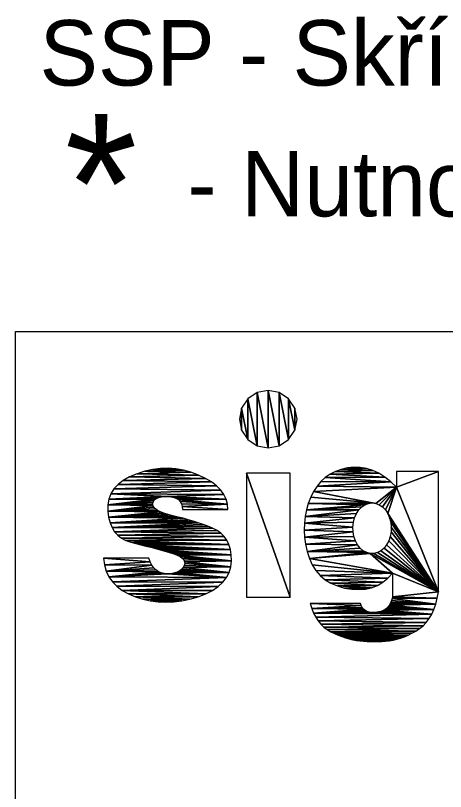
# Model space of a CAD drawing. Extents: x -614134 to -613504, y -1110668 to -1110371.
# Drawn here: x -613676 to -613656.3, y -1110630.88 to -1110595.29 of the extents above; entities that cross this region are included whole.
import ezdxf

# ---------------------------------------------------------------- set-up
doc = ezdxf.new("R2010")
doc.units = 0
doc.layers.add('Vrstva 1', color=7, linetype='Continuous')

msp = doc.modelspace()

# ---------------------------------------------------------------- linework, layer by layer
at = {"layer": 'Vrstva 1'}
for points in [[(-613676, -1110609.774), (-613511, -1110609.774), (-613511, -1110662), (-613676, -1110662)], [(-613676, -1110609.774), (-613511, -1110609.774), (-613511, -1110662), (-613676, -1110662)], [(-613664.926, -1110612.582), (-613664.42, -1110615.122), (-613664.42, -1110612.482)], [(-613664.42, -1110612.482), (-613663.915, -1110615.022), (-613663.915, -1110612.582)], [(-613663.915, -1110615.022), (-613664.42, -1110612.482), (-613664.42, -1110615.122)], [(-613665.354, -1110612.868), (-613664.926, -1110615.022), (-613664.926, -1110612.582)], [(-613664.42, -1110615.122), (-613664.926, -1110612.582), (-613664.926, -1110615.022)], [(-613663.915, -1110612.582), (-613663.487, -1110614.736), (-613663.487, -1110612.868)], [(-613663.487, -1110614.736), (-613663.915, -1110612.582), (-613663.915, -1110615.022)], [(-613665.64, -1110613.298), (-613665.354, -1110614.736), (-613665.354, -1110612.868)], [(-613664.926, -1110615.022), (-613665.354, -1110612.868), (-613665.354, -1110614.736)], [(-613663.487, -1110612.868), (-613663.201, -1110614.308), (-613663.201, -1110613.298)], [(-613663.201, -1110614.308), (-613663.487, -1110612.868), (-613663.487, -1110614.736)], [(-613665.74, -1110613.802), (-613665.64, -1110614.308), (-613665.64, -1110613.298)], [(-613665.354, -1110614.736), (-613665.64, -1110613.298), (-613665.64, -1110614.308)], [(-613663.1, -1110613.802), (-613663.201, -1110613.298), (-613663.201, -1110614.308)], [(-613669.359, -1110616.064), (-613669.714, -1110616.108), (-613668.656, -1110616.078)], [(-613669.006, -1110616.054), (-613669.359, -1110616.064), (-613668.656, -1110616.078)], [(-613660.788, -1110616.038), (-613661.076, -1110616.106), (-613659.913, -1110616.062)], [(-613659.913, -1110616.062), (-613661.076, -1110616.106), (-613659.63, -1110616.152)], [(-613660.492, -1110616.006), (-613660.788, -1110616.038), (-613660.201, -1110616.012)], [(-613660.201, -1110616.012), (-613660.788, -1110616.038), (-613659.913, -1110616.062)], [(-613670.434, -1110616.302), (-613670.772, -1110616.444), (-613667.621, -1110616.362)], [(-613667.621, -1110616.362), (-613670.772, -1110616.444), (-613667.301, -1110616.516)], [(-613670.073, -1110616.188), (-613670.434, -1110616.302), (-613667.963, -1110616.232)], [(-613667.963, -1110616.232), (-613670.434, -1110616.302), (-613667.621, -1110616.362)], [(-613669.714, -1110616.108), (-613670.073, -1110616.188), (-613668.308, -1110616.138)], [(-613668.308, -1110616.138), (-613670.073, -1110616.188), (-613667.963, -1110616.232)], [(-613668.656, -1110616.078), (-613669.714, -1110616.108), (-613668.308, -1110616.138)], [(-613663.42, -1110621.962), (-613663.42, -1110616.282), (-613665.42, -1110616.282)], [(-613665.42, -1110616.282), (-613665.42, -1110621.962), (-613663.42, -1110621.962)], [(-613661.585, -1110616.33), (-613661.806, -1110616.482), (-613659.077, -1110616.454)], [(-613661.341, -1110616.204), (-613661.585, -1110616.33), (-613659.351, -1110616.282)], [(-613659.351, -1110616.282), (-613661.585, -1110616.33), (-613659.077, -1110616.454)], [(-613661.076, -1110616.106), (-613661.341, -1110616.204), (-613659.63, -1110616.152)], [(-613659.63, -1110616.152), (-613661.341, -1110616.204), (-613659.351, -1110616.282)], [(-613656.62, -1110616.202), (-613658.54, -1110616.922), (-613656.62, -1110621.722)], [(-613658.54, -1110616.202), (-613658.54, -1110616.922), (-613656.62, -1110616.202)], [(-613671.061, -1110616.608), (-613671.302, -1110616.79), (-613667.025, -1110616.682)], [(-613667.025, -1110616.682), (-613671.302, -1110616.79), (-613666.791, -1110616.86)], [(-613670.772, -1110616.444), (-613671.061, -1110616.608), (-613667.301, -1110616.516)], [(-613667.301, -1110616.516), (-613671.061, -1110616.608), (-613667.025, -1110616.682)], [(-613662.006, -1110616.666), (-613662.185, -1110616.876), (-613658.807, -1110616.668)], [(-613658.807, -1110616.668), (-613662.185, -1110616.876), (-613658.54, -1110616.922)], [(-613661.806, -1110616.482), (-613662.006, -1110616.666), (-613658.807, -1110616.668)], [(-613659.077, -1110616.454), (-613661.806, -1110616.482), (-613658.807, -1110616.668)], [(-613671.494, -1110616.994), (-613671.637, -1110617.22), (-613666.6, -1110617.052)], [(-613666.6, -1110617.052), (-613671.637, -1110617.22), (-613666.452, -1110617.256)], [(-613671.302, -1110616.79), (-613671.494, -1110616.994), (-613666.791, -1110616.86)], [(-613666.791, -1110616.86), (-613671.494, -1110616.994), (-613666.6, -1110617.052)], [(-613662.341, -1110617.116), (-613662.476, -1110617.384), (-613659.66, -1110617.642)], [(-613662.185, -1110616.876), (-613662.341, -1110617.116), (-613658.54, -1110616.922)], [(-613658.54, -1110616.922), (-613662.341, -1110617.116), (-613659.494, -1110617.664)], [(-613662.341, -1110617.116), (-613659.66, -1110617.642), (-613659.494, -1110617.664)], [(-613658.54, -1110616.922), (-613659.494, -1110617.664), (-613659.333, -1110617.726)], [(-613658.54, -1110616.922), (-613659.333, -1110617.726), (-613659.185, -1110617.826)], [(-613658.54, -1110616.922), (-613659.185, -1110617.826), (-613659.053, -1110617.962)], [(-613658.54, -1110616.922), (-613659.053, -1110617.962), (-613658.944, -1110618.13)], [(-613658.54, -1110616.922), (-613658.944, -1110618.13), (-613656.62, -1110621.722)], [(-613671.732, -1110617.464), (-613671.778, -1110617.73), (-613669.602, -1110617.474)], [(-613669.602, -1110617.474), (-613671.778, -1110617.73), (-613669.658, -1110617.532)], [(-613671.637, -1110617.22), (-613671.732, -1110617.464), (-613669.179, -1110617.35)], [(-613669.179, -1110617.35), (-613671.732, -1110617.464), (-613669.314, -1110617.364)], [(-613669.314, -1110617.364), (-613671.732, -1110617.464), (-613669.43, -1110617.39)], [(-613669.43, -1110617.39), (-613671.732, -1110617.464), (-613669.526, -1110617.426)], [(-613669.526, -1110617.426), (-613671.732, -1110617.464), (-613669.602, -1110617.474)], [(-613671.637, -1110617.22), (-613669.023, -1110617.346), (-613666.452, -1110617.256)], [(-613671.637, -1110617.22), (-613669.179, -1110617.35), (-613669.023, -1110617.346)], [(-613666.452, -1110617.256), (-613669.023, -1110617.346), (-613666.347, -1110617.474)], [(-613669.023, -1110617.346), (-613668.868, -1110617.358), (-613666.347, -1110617.474)], [(-613668.868, -1110617.358), (-613668.733, -1110617.386), (-613666.347, -1110617.474)], [(-613668.733, -1110617.386), (-613668.618, -1110617.434), (-613666.347, -1110617.474)], [(-613668.618, -1110617.434), (-613668.523, -1110617.5), (-613666.347, -1110617.474)], [(-613666.347, -1110617.474), (-613668.523, -1110617.5), (-613666.285, -1110617.702)], [(-613662.476, -1110617.384), (-613662.587, -1110617.67), (-613659.66, -1110617.642)], [(-613669.658, -1110617.532), (-613671.778, -1110617.73), (-613669.694, -1110617.6)], [(-613669.694, -1110617.6), (-613671.778, -1110617.73), (-613669.711, -1110617.68)], [(-613669.711, -1110617.68), (-613671.778, -1110617.73), (-613669.702, -1110617.764)], [(-613671.778, -1110617.73), (-613671.776, -1110618.016), (-613669.702, -1110617.764)], [(-613669.702, -1110617.764), (-613671.776, -1110618.016), (-613669.663, -1110617.842)], [(-613669.663, -1110617.842), (-613671.776, -1110618.016), (-613669.594, -1110617.918)], [(-613668.523, -1110617.5), (-613668.449, -1110617.584), (-613666.285, -1110617.702)], [(-613668.449, -1110617.584), (-613668.394, -1110617.686), (-613666.285, -1110617.702)], [(-613668.394, -1110617.686), (-613668.359, -1110617.806), (-613666.285, -1110617.702)], [(-613666.285, -1110617.702), (-613668.359, -1110617.806), (-613666.266, -1110617.944)], [(-613668.359, -1110617.806), (-613668.345, -1110617.944), (-613666.266, -1110617.944)], [(-613662.587, -1110617.67), (-613662.671, -1110617.962), (-613659.988, -1110617.726)], [(-613659.988, -1110617.726), (-613662.671, -1110617.962), (-613660.136, -1110617.826)], [(-613660.136, -1110617.826), (-613662.671, -1110617.962), (-613660.268, -1110617.962)], [(-613659.66, -1110617.642), (-613662.587, -1110617.67), (-613659.827, -1110617.664)], [(-613659.827, -1110617.664), (-613662.587, -1110617.67), (-613659.988, -1110617.726)], [(-613669.594, -1110617.918), (-613671.776, -1110618.016), (-613669.494, -1110617.988)], [(-613669.494, -1110617.988), (-613671.776, -1110618.016), (-613669.364, -1110618.056)], [(-613671.776, -1110618.016), (-613671.736, -1110618.296), (-613669.364, -1110618.056)], [(-613669.364, -1110618.056), (-613671.736, -1110618.296), (-613669.203, -1110618.118)], [(-613669.203, -1110618.118), (-613671.736, -1110618.296), (-613669.012, -1110618.178)], [(-613669.012, -1110618.178), (-613671.736, -1110618.296), (-613668.79, -1110618.232)], [(-613660.268, -1110617.962), (-613662.73, -1110618.262), (-613660.377, -1110618.13)], [(-613662.671, -1110617.962), (-613662.73, -1110618.262), (-613660.268, -1110617.962)], [(-613660.377, -1110618.13), (-613662.73, -1110618.262), (-613660.461, -1110618.32)], [(-613658.944, -1110618.13), (-613658.86, -1110618.32), (-613656.62, -1110621.722)], [(-613668.79, -1110618.232), (-613671.736, -1110618.296), (-613668.554, -1110618.288)], [(-613668.554, -1110618.288), (-613671.736, -1110618.296), (-613668.321, -1110618.348)], [(-613671.736, -1110618.296), (-613671.67, -1110618.548), (-613668.321, -1110618.348)], [(-613668.321, -1110618.348), (-613671.67, -1110618.548), (-613668.09, -1110618.412)], [(-613668.09, -1110618.412), (-613671.67, -1110618.548), (-613667.861, -1110618.48)], [(-613667.861, -1110618.48), (-613671.67, -1110618.548), (-613667.635, -1110618.554)], [(-613671.67, -1110618.548), (-613671.578, -1110618.772), (-613667.635, -1110618.554)], [(-613667.635, -1110618.554), (-613671.578, -1110618.772), (-613667.41, -1110618.63)], [(-613662.73, -1110618.262), (-613662.763, -1110618.57), (-613660.461, -1110618.32)], [(-613660.461, -1110618.32), (-613662.763, -1110618.57), (-613660.516, -1110618.528)], [(-613660.516, -1110618.528), (-613662.763, -1110618.57), (-613660.539, -1110618.748)], [(-613658.86, -1110618.32), (-613658.805, -1110618.528), (-613656.62, -1110621.722)], [(-613658.805, -1110618.528), (-613658.781, -1110618.748), (-613656.62, -1110621.722)], [(-613667.41, -1110618.63), (-613671.578, -1110618.772), (-613667.189, -1110618.712)], [(-613667.189, -1110618.712), (-613671.578, -1110618.772), (-613666.969, -1110618.798)], [(-613671.578, -1110618.772), (-613671.46, -1110618.964), (-613666.969, -1110618.798)], [(-613666.969, -1110618.798), (-613671.46, -1110618.964), (-613666.764, -1110618.9)], [(-613666.764, -1110618.9), (-613671.46, -1110618.964), (-613666.587, -1110619.024)], [(-613662.763, -1110618.57), (-613662.77, -1110618.884), (-613660.539, -1110618.748)], [(-613660.539, -1110618.748), (-613662.77, -1110618.884), (-613660.532, -1110618.968)], [(-613662.77, -1110618.884), (-613662.752, -1110619.206), (-613660.532, -1110618.968)], [(-613658.781, -1110618.748), (-613658.789, -1110618.968), (-613656.62, -1110621.722)], [(-613671.46, -1110618.964), (-613671.315, -1110619.128), (-613666.587, -1110619.024)], [(-613666.587, -1110619.024), (-613671.315, -1110619.128), (-613666.438, -1110619.174)], [(-613671.315, -1110619.128), (-613671.144, -1110619.262), (-613666.438, -1110619.174)], [(-613666.438, -1110619.174), (-613671.144, -1110619.262), (-613666.317, -1110619.35)], [(-613671.144, -1110619.262), (-613670.947, -1110619.366), (-613666.317, -1110619.35)], [(-613660.532, -1110618.968), (-613662.752, -1110619.206), (-613660.492, -1110619.182)], [(-613660.492, -1110619.182), (-613662.752, -1110619.206), (-613660.423, -1110619.382)], [(-613662.752, -1110619.206), (-613662.707, -1110619.536), (-613660.423, -1110619.382)], [(-613658.829, -1110619.182), (-613658.898, -1110619.382), (-613656.62, -1110621.722)], [(-613658.789, -1110618.968), (-613658.829, -1110619.182), (-613656.62, -1110621.722)], [(-613666.317, -1110619.35), (-613670.947, -1110619.366), (-613666.223, -1110619.55)], [(-613670.947, -1110619.366), (-613670.723, -1110619.44), (-613666.223, -1110619.55)], [(-613670.723, -1110619.44), (-613670.489, -1110619.5), (-613666.223, -1110619.55)], [(-613670.489, -1110619.5), (-613670.257, -1110619.56), (-613666.223, -1110619.55)], [(-613666.223, -1110619.55), (-613670.257, -1110619.56), (-613666.157, -1110619.774)], [(-613670.257, -1110619.56), (-613670.03, -1110619.618), (-613666.157, -1110619.774)], [(-613670.03, -1110619.618), (-613669.806, -1110619.678), (-613666.157, -1110619.774)], [(-613660.423, -1110619.382), (-613662.707, -1110619.536), (-613660.326, -1110619.562)], [(-613662.707, -1110619.536), (-613662.636, -1110619.872), (-613660.326, -1110619.562)], [(-613660.326, -1110619.562), (-613662.636, -1110619.872), (-613660.204, -1110619.714)], [(-613658.995, -1110619.562), (-613659.116, -1110619.714), (-613656.62, -1110621.722)], [(-613658.898, -1110619.382), (-613658.995, -1110619.562), (-613656.62, -1110621.722)], [(-613669.806, -1110619.678), (-613669.586, -1110619.736), (-613666.157, -1110619.774)], [(-613669.586, -1110619.736), (-613669.369, -1110619.794), (-613666.157, -1110619.774)], [(-613666.157, -1110619.774), (-613669.369, -1110619.794), (-613666.119, -1110620.022)], [(-613669.369, -1110619.794), (-613669.156, -1110619.852), (-613666.119, -1110620.022)], [(-613669.156, -1110619.852), (-613668.946, -1110619.91), (-613666.119, -1110620.022)], [(-613668.946, -1110619.91), (-613668.754, -1110619.97), (-613666.119, -1110620.022)], [(-613668.754, -1110619.97), (-613668.592, -1110620.036), (-613666.119, -1110620.022)], [(-613660.204, -1110619.714), (-613662.636, -1110619.872), (-613660.064, -1110619.834)], [(-613660.064, -1110619.834), (-613662.636, -1110619.872), (-613659.908, -1110619.916)], [(-613662.636, -1110619.872), (-613662.536, -1110620.194), (-613659.908, -1110619.916)], [(-613659.908, -1110619.916), (-613662.536, -1110620.194), (-613659.744, -1110619.958)], [(-613659.744, -1110619.958), (-613662.536, -1110620.194), (-613658.728, -1110620.868)], [(-613659.744, -1110619.958), (-613658.728, -1110620.868), (-613656.62, -1110621.722)], [(-613656.62, -1110621.722), (-613659.577, -1110619.958), (-613659.744, -1110619.958)], [(-613659.413, -1110619.916), (-613659.577, -1110619.958), (-613656.62, -1110621.722)], [(-613659.257, -1110619.834), (-613659.413, -1110619.916), (-613656.62, -1110621.722)], [(-613659.116, -1110619.714), (-613659.257, -1110619.834), (-613656.62, -1110621.722)], [(-613669.827, -1110620.346), (-613669.888, -1110620.176), (-613671.969, -1110620.176)], [(-613671.969, -1110620.176), (-613671.925, -1110620.484), (-613669.827, -1110620.346)], [(-613666.119, -1110620.022), (-613668.592, -1110620.036), (-613666.108, -1110620.296)], [(-613668.592, -1110620.036), (-613668.462, -1110620.104), (-613666.108, -1110620.296)], [(-613668.462, -1110620.104), (-613668.362, -1110620.178), (-613666.108, -1110620.296)], [(-613668.362, -1110620.178), (-613668.294, -1110620.256), (-613666.108, -1110620.296)], [(-613668.294, -1110620.256), (-613668.256, -1110620.338), (-613666.108, -1110620.296)], [(-613666.108, -1110620.296), (-613668.256, -1110620.338), (-613666.135, -1110620.572)], [(-613662.536, -1110620.194), (-613662.403, -1110620.486), (-613658.728, -1110620.868)], [(-613669.827, -1110620.346), (-613671.925, -1110620.484), (-613669.753, -1110620.492)], [(-613671.925, -1110620.484), (-613671.842, -1110620.766), (-613669.753, -1110620.492)], [(-613669.753, -1110620.492), (-613671.842, -1110620.766), (-613669.667, -1110620.616)], [(-613669.667, -1110620.616), (-613671.842, -1110620.766), (-613669.568, -1110620.716)], [(-613668.381, -1110620.68), (-613668.456, -1110620.744), (-613666.208, -1110620.828)], [(-613668.32, -1110620.604), (-613668.381, -1110620.68), (-613666.208, -1110620.828)], [(-613668.273, -1110620.516), (-613668.32, -1110620.604), (-613666.135, -1110620.572)], [(-613666.135, -1110620.572), (-613668.32, -1110620.604), (-613666.208, -1110620.828)], [(-613668.249, -1110620.424), (-613668.273, -1110620.516), (-613666.135, -1110620.572)], [(-613668.256, -1110620.338), (-613668.249, -1110620.424), (-613666.135, -1110620.572)], [(-613662.403, -1110620.486), (-613662.238, -1110620.744), (-613658.728, -1110620.868)], [(-613669.568, -1110620.716), (-613671.842, -1110620.766), (-613669.456, -1110620.796)], [(-613671.842, -1110620.766), (-613671.718, -1110621.024), (-613669.456, -1110620.796)], [(-613669.456, -1110620.796), (-613671.718, -1110621.024), (-613669.333, -1110620.85)], [(-613669.333, -1110620.85), (-613671.718, -1110621.024), (-613669.197, -1110620.884)], [(-613669.197, -1110620.884), (-613671.718, -1110621.024), (-613669.049, -1110620.894)], [(-613669.049, -1110620.894), (-613671.718, -1110621.024), (-613666.328, -1110621.064)], [(-613671.718, -1110621.024), (-613671.556, -1110621.258), (-613666.328, -1110621.064)], [(-613668.901, -1110620.888), (-613669.049, -1110620.894), (-613666.328, -1110621.064)], [(-613668.768, -1110620.87), (-613668.901, -1110620.888), (-613666.328, -1110621.064)], [(-613668.65, -1110620.84), (-613668.768, -1110620.87), (-613666.328, -1110621.064)], [(-613668.546, -1110620.798), (-613668.65, -1110620.84), (-613666.208, -1110620.828)], [(-613666.208, -1110620.828), (-613668.65, -1110620.84), (-613666.328, -1110621.064)], [(-613668.456, -1110620.744), (-613668.546, -1110620.798), (-613666.208, -1110620.828)], [(-613662.238, -1110620.744), (-613662.04, -1110620.968), (-613658.728, -1110620.868)], [(-613658.728, -1110620.868), (-613662.04, -1110620.968), (-613658.94, -1110621.096)], [(-613662.04, -1110620.968), (-613661.809, -1110621.162), (-613658.94, -1110621.096)], [(-613658.728, -1110620.868), (-613658.728, -1110621.946), (-613656.62, -1110621.722)], [(-613666.328, -1110621.064), (-613671.556, -1110621.258), (-613666.496, -1110621.28)], [(-613671.556, -1110621.258), (-613671.354, -1110621.466), (-613666.496, -1110621.28)], [(-613666.496, -1110621.28), (-613671.354, -1110621.466), (-613666.71, -1110621.476)], [(-613658.94, -1110621.096), (-613661.809, -1110621.162), (-613659.17, -1110621.282)], [(-613661.809, -1110621.162), (-613661.546, -1110621.322), (-613659.17, -1110621.282)], [(-613659.17, -1110621.282), (-613661.546, -1110621.322), (-613659.417, -1110621.426)], [(-613661.546, -1110621.322), (-613661.25, -1110621.448), (-613659.417, -1110621.426)], [(-613671.354, -1110621.466), (-613671.112, -1110621.652), (-613666.71, -1110621.476)], [(-613666.71, -1110621.476), (-613671.112, -1110621.652), (-613666.971, -1110621.652)], [(-613671.112, -1110621.652), (-613670.83, -1110621.812), (-613667.279, -1110621.808)], [(-613666.971, -1110621.652), (-613671.112, -1110621.652), (-613667.279, -1110621.808)], [(-613659.417, -1110621.426), (-613661.25, -1110621.448), (-613659.682, -1110621.532)], [(-613661.25, -1110621.448), (-613660.921, -1110621.544), (-613659.682, -1110621.532)], [(-613659.682, -1110621.532), (-613660.921, -1110621.544), (-613659.965, -1110621.596)], [(-613660.921, -1110621.544), (-613660.585, -1110621.602), (-613659.965, -1110621.596)], [(-613659.965, -1110621.596), (-613660.585, -1110621.602), (-613660.266, -1110621.618)], [(-613656.62, -1110621.722), (-613658.728, -1110621.946), (-613656.674, -1110622.014)], [(-613667.279, -1110621.808), (-613670.83, -1110621.812), (-613667.634, -1110621.944)], [(-613670.83, -1110621.812), (-613670.509, -1110621.95), (-613667.634, -1110621.944)], [(-613667.634, -1110621.944), (-613670.509, -1110621.95), (-613668.009, -1110622.054)], [(-613670.509, -1110621.95), (-613670.166, -1110622.058), (-613668.009, -1110622.054)], [(-613668.009, -1110622.054), (-613670.166, -1110622.058), (-613668.381, -1110622.134)], [(-613670.166, -1110622.058), (-613669.819, -1110622.136), (-613668.381, -1110622.134)], [(-613658.77, -1110622.114), (-613658.798, -1110622.19), (-613656.743, -1110622.282)], [(-613658.747, -1110622.032), (-613658.77, -1110622.114), (-613656.743, -1110622.282)], [(-613658.728, -1110621.946), (-613658.747, -1110622.032), (-613656.674, -1110622.014)], [(-613656.674, -1110622.014), (-613658.747, -1110622.032), (-613656.743, -1110622.282)], [(-613668.381, -1110622.134), (-613669.819, -1110622.136), (-613668.747, -1110622.18)], [(-613669.819, -1110622.136), (-613669.466, -1110622.182), (-613668.747, -1110622.18)], [(-613668.747, -1110622.18), (-613669.466, -1110622.182), (-613669.109, -1110622.198)], [(-613660.157, -1110622.35), (-613660.19, -1110622.252), (-613662.497, -1110622.252)], [(-613662.497, -1110622.252), (-613662.428, -1110622.48), (-613660.157, -1110622.35)], [(-613660.157, -1110622.35), (-613662.428, -1110622.48), (-613660.115, -1110622.436)], [(-613660.115, -1110622.436), (-613662.428, -1110622.48), (-613660.062, -1110622.508)], [(-613658.953, -1110622.436), (-613659.003, -1110622.484), (-613656.828, -1110622.526)], [(-613658.907, -1110622.384), (-613658.953, -1110622.436), (-613656.828, -1110622.526)], [(-613658.866, -1110622.324), (-613658.907, -1110622.384), (-613656.828, -1110622.526)], [(-613658.83, -1110622.26), (-613658.866, -1110622.324), (-613656.743, -1110622.282)], [(-613656.743, -1110622.282), (-613658.866, -1110622.324), (-613656.828, -1110622.526)], [(-613658.798, -1110622.19), (-613658.83, -1110622.26), (-613656.743, -1110622.282)], [(-613662.428, -1110622.48), (-613662.344, -1110622.69), (-613660.062, -1110622.508)], [(-613660.062, -1110622.508), (-613662.344, -1110622.69), (-613659.999, -1110622.566)], [(-613659.999, -1110622.566), (-613662.344, -1110622.69), (-613659.926, -1110622.61)], [(-613659.926, -1110622.61), (-613662.344, -1110622.69), (-613659.843, -1110622.642)], [(-613659.843, -1110622.642), (-613662.344, -1110622.69), (-613659.75, -1110622.662)], [(-613659.75, -1110622.662), (-613662.344, -1110622.69), (-613659.646, -1110622.666)], [(-613659.646, -1110622.666), (-613662.344, -1110622.69), (-613656.929, -1110622.748)], [(-613662.344, -1110622.69), (-613662.247, -1110622.88), (-613656.929, -1110622.748)], [(-613656.929, -1110622.748), (-613662.247, -1110622.88), (-613657.045, -1110622.948)], [(-613659.541, -1110622.662), (-613659.646, -1110622.666), (-613656.929, -1110622.748)], [(-613659.443, -1110622.654), (-613659.541, -1110622.662), (-613656.929, -1110622.748)], [(-613659.352, -1110622.638), (-613659.443, -1110622.654), (-613656.929, -1110622.748)], [(-613659.268, -1110622.618), (-613659.352, -1110622.638), (-613656.929, -1110622.748)], [(-613659.191, -1110622.592), (-613659.268, -1110622.618), (-613656.929, -1110622.748)], [(-613659.121, -1110622.562), (-613659.191, -1110622.592), (-613656.929, -1110622.748)], [(-613656.828, -1110622.526), (-613659.121, -1110622.562), (-613656.929, -1110622.748)], [(-613659.058, -1110622.526), (-613659.121, -1110622.562), (-613656.828, -1110622.526)], [(-613659.003, -1110622.484), (-613659.058, -1110622.526), (-613656.828, -1110622.526)], [(-613662.247, -1110622.88), (-613662.136, -1110623.05), (-613657.045, -1110622.948)], [(-613657.045, -1110622.948), (-613662.136, -1110623.05), (-613657.178, -1110623.124)], [(-613662.136, -1110623.05), (-613662.012, -1110623.204), (-613657.178, -1110623.124)], [(-613657.178, -1110623.124), (-613662.012, -1110623.204), (-613657.326, -1110623.276)], [(-613662.012, -1110623.204), (-613661.873, -1110623.338), (-613657.326, -1110623.276)], [(-613657.326, -1110623.276), (-613661.873, -1110623.338), (-613657.491, -1110623.406)], [(-613661.873, -1110623.338), (-613661.721, -1110623.452), (-613657.491, -1110623.406)], [(-613657.491, -1110623.406), (-613661.721, -1110623.452), (-613657.663, -1110623.518)], [(-613661.721, -1110623.452), (-613661.555, -1110623.548), (-613657.663, -1110623.518)], [(-613657.663, -1110623.518), (-613661.555, -1110623.548), (-613657.836, -1110623.618)], [(-613661.555, -1110623.548), (-613661.383, -1110623.632), (-613657.836, -1110623.618)], [(-613657.836, -1110623.618), (-613661.383, -1110623.632), (-613658.008, -1110623.704)], [(-613661.383, -1110623.632), (-613661.212, -1110623.706), (-613658.008, -1110623.704)], [(-613658.008, -1110623.704), (-613661.212, -1110623.706), (-613658.182, -1110623.78)], [(-613661.212, -1110623.706), (-613661.043, -1110623.772), (-613658.182, -1110623.78)], [(-613661.043, -1110623.772), (-613660.875, -1110623.828), (-613658.182, -1110623.78)], [(-613658.182, -1110623.78), (-613660.875, -1110623.828), (-613658.355, -1110623.844)], [(-613660.875, -1110623.828), (-613660.709, -1110623.876), (-613658.355, -1110623.844)], [(-613658.355, -1110623.844), (-613660.709, -1110623.876), (-613658.529, -1110623.894)], [(-613660.709, -1110623.876), (-613660.544, -1110623.916), (-613658.529, -1110623.894)], [(-613658.529, -1110623.894), (-613660.544, -1110623.916), (-613658.703, -1110623.934)], [(-613660.544, -1110623.916), (-613660.381, -1110623.948), (-613658.703, -1110623.934)], [(-613658.703, -1110623.934), (-613660.381, -1110623.948), (-613658.877, -1110623.96)], [(-613660.381, -1110623.948), (-613660.219, -1110623.97), (-613658.877, -1110623.96)], [(-613658.877, -1110623.96), (-613660.219, -1110623.97), (-613659.05, -1110623.978)], [(-613660.219, -1110623.97), (-613660.057, -1110623.986), (-613659.05, -1110623.978)], [(-613659.05, -1110623.978), (-613660.057, -1110623.986), (-613659.222, -1110623.992)], [(-613660.057, -1110623.986), (-613659.893, -1110623.998), (-613659.222, -1110623.992)], [(-613659.222, -1110623.992), (-613659.893, -1110623.998), (-613659.393, -1110624)], [(-613659.893, -1110623.998), (-613659.728, -1110624.004), (-613659.393, -1110624)], [(-613659.393, -1110624), (-613659.728, -1110624.004), (-613659.561, -1110624.004)]]:
    msp.add_lwpolyline(points, close=True, dxfattribs=at)

# ---------------------------------------------------------------- texts
for s, p in [('SSP - Skříň společná přístrojová', (-613674.9, -1110598.5)), ('   - Nutno dodržet minimální délku 10m', (-613671.462, -1110604.5))]:
    msp.add_text(s, height=3, dxfattribs=at).set_placement(p)
msp.add_text('*', height=6.4, rotation=360, dxfattribs=at).set_placement((-613673.747, -1110606.2))

doc.saveas('drawing.dxf')
